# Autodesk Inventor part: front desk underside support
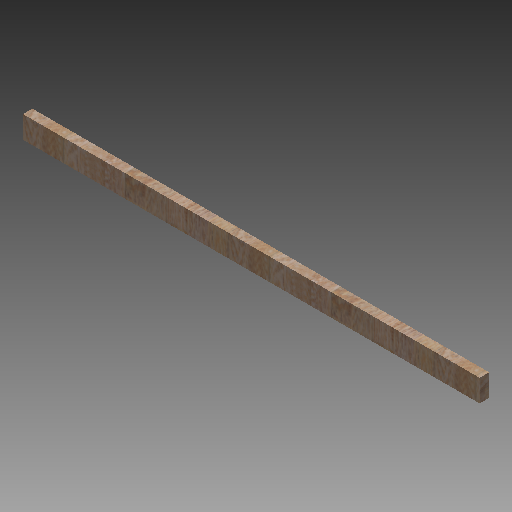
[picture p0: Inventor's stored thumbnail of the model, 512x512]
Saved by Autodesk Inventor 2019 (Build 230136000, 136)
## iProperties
Created: 2013-07
Part Number: front desk underside support
Material: Generic
Document SubType Name: Modeling
Designer: Patrick Rice
Density: 1 g/cm^3
Appearance: Default
Author: Patrick Rice
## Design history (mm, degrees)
sketch "Sketch1"
  geometry: L1 (44.45, -19.05)-(-44.45, -19.05); L2 (-44.45, -19.05)-(-44.45, 19.05); L3 (-44.45, 19.05)-(44.45, 19.05); L4 (44.45, 19.05)-(44.45, -19.05); L5 (44.45, -19.05)-(-44.45, 19.05); L6 (-44.45, -19.05)-(44.45, 19.05); 1 further point
  constraints: 12 end point, 2 midpoint, 2 parallel, 1 horizontal, 1 perpendicular
  dimensions: "d0" = 88.9 distance of L2.end L3.end; "d1" = 38.1 distance of L1.end L2.end
extrude "Extrusion1" new body sketch "Sketch1" distance "d2" = 1828.8; taper "d3" = 0 deg
body "Solid1"
